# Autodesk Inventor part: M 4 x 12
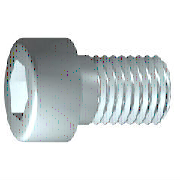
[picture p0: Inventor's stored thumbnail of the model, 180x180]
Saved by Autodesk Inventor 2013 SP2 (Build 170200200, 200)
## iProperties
IsCustomPart: 0
Created: 2009-02
Part Number: M 4 x 12
Material: 강, 연강
Description: 6각머리 태핑 나사
Document SubType Name: Modeling
Standard: KS B 1003
Designer: KYOUNG IL JANG
Standards Organization: KS
Language: ko-KR
Size Designation: M 4 x 12
Categories: <MemberInstance><Categories><Category DisplayName="조임쇠" InternalName="e4da775c-781d-43d5-af7c-5136215cf5a6" Mnemonic="FSTN"><Category DisplayName="볼트" InternalN
Density: 7.86 g/cm^3
Mass: 2.23465 g
Surface Area: 3.30853 cm^2
Volume: 0.284306 cm^3
Author: KYOUNG IL JANG
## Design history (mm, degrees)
sketch "스케치1"
  geometry: L1 (-1, 0)-(12, 0); L2 (12, 0)-(12, 2); L3 (12, 2)-(1.75, 2); L4 (1.75, 2)-(1.32, 2); L5 (1.32, 2)-(0, 2); L6 (0, 2)-(0, 3.5); L7 (0, 3.5)-(-4, 3.5); L8 (-4, 3.5)-(-4, 1.732); L9 (-4, 1.732)-(-2, 1.732); L10 (-2, 1.732)-(-1, 0); L11 (-7.2, 0)-(15.2, 0) reference; L12 (0, -0.7)-(0, 4.2) reference; L13 (1.75, 2)-(0, 2)
  constraints: 22 end point, 6 parallel, 2 collinear, 2 perpendicular, 1 horizontal, 1 point on line
  dimensions: "d1" = 10.25 distance from line of L3.end L2 (= GEL); "d2" = 0.42952 distance of L4.end L3.end (computed from GAL); "d3" = 4 distance between parallel lines of L8 L6 (= KOH); "d4" = 2 distance of L8.end L9.end (= INTI); "d5" = 60 deg angle of L10 L1; "d6" = 4 diameter of L3 L1 (= GD); "d7" = 4 diameter of L5 L1 (= BDM); "d8" = 3.4641 diameter of L9 L1 (= 1.1547 x SW); "d9" = 7 diameter of L7 L1 (= KOD); "d26" = 12 distance between parallel lines of L12 L2 (= NLG)
revolve "본체" sketch "스케치1" stored, may be unused: angle "d10" = 90 deg
sketch "스케치2"
  geometry: L1 (0, -4.9)-(0, 4.9) reference; L2 (-4.9, 0)-(4.9, 0) reference; L3 (1.732, 0)-(0.866, -1.5); L4 (0.866, -1.5)-(-0.866, -1.5); L5 (-0.866, -1.5)-(-1.732, 0); L6 (-1.732, 0)-(-0.866, 1.5); L7 (-0.866, 1.5)-(0.866, 1.5); L8 (0.866, 1.5)-(1.732, 0); 2 further points
  constraints: 12 end point, 1 coincident, 1 horizontal alignment, 1 point on line, 12 other
extrude "슬롯" join sketch "스케치2" stored distance "d11" = 10; taper "d12" = 0 deg
workplane "Work Plane1"
fillet "Fillet2" dims "d30" = 0.1 (= R)
body "Solid1"
fillet "모깎기1" dims "d17" = 0.4 (= RR)
feature "스레드" dims "d13" = 10.25 (= GEL), "d14" = 0
chamfer "모따기1" distance "d15" = 0.42941 (= -0.5 x SPD + 0.5 x GD); stored, may be unused: second distance "d16" = 0.42941 (= GUL), angle "d27" = 45 deg
other parameters: "GD" = 4 (= NND) [user parameter; used in 2 equation terms], "NLG" = 12 [user parameter; used in 1 equation term], "GEL" = 10.25 [user parameter; used in 2 equation terms], "KOD" = 7 [user parameter; used in 1 equation term], "KOH" = 4 [user parameter; used in 1 equation term], "INTI" = 2 [user parameter; used in 1 equation term], "GAL" = 0.42941 (= 0.61345 x PTC) [user parameter; used in 1 equation term], "GUL" = 0.42941 (= 0.61345 x PTC) [user parameter; used in 1 equation term], "BDM" = 4 (= NND) [user parameter; used in 1 equation term], "SW" = 3 [user parameter; used in 2 equation terms], "RR" = 0.4 [user parameter; used in 1 equation term], "SPD" = 3.14117 (= NND - 1.2269 x PTC) [user parameter; used in 1 equation term], "d19" = 0, "d28" = 0, "d29" = 0, "R" = 0.1 [user parameter; used in 1 equation term], "PHH" = 0.2 [user parameter], "GD1" = 3.14117 (= THREADDIA - 1.2269 x PTC) [user parameter], "THREADDIA" = 4 [user parameter; used in 1 equation term], "FAWI" = 45 deg [user parameter], "TPU" = 14.28571 (computed from PTC) [user parameter], "PTC" = 0.7 [user parameter; used in 5 equation terms], "NND" = 4 [user parameter; used in 3 equation terms], "TOA" = 30 deg [user parameter], "E0" = 3.465 (= 1.155 x SW) [user parameter]
